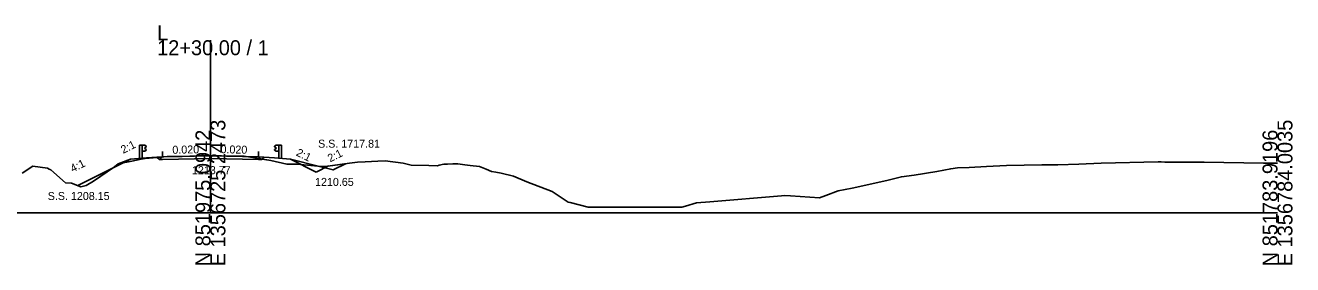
# Model space of a CAD drawing. Extents: x -26 to 4603, y -10 to 4066.
# Drawn here: x 1565.3 to 1802.8, y 490.3 to 535.2 of the extents above; entities that cross this region are included whole.
import ezdxf

# ---------------------------------------------------------------- set-up
doc = ezdxf.new("R2010")
doc.units = 0
for name, color, linetype in [('Exist Cross Section Cell', 7, 'Continuous'), ('Exist XS Center Line Elevation Label', 7, 'Continuous'), ('Exist XS Ground Line', 7, 'Continuous'), ('Prop XS Ditch Standard Text', 7, 'Continuous'), ('Prop XS Dump Level', 7, 'Continuous'), ('Prop XS Earthwork Shape', 7, 'Continuous'), ('Prop XS EOT Tick Mark', 7, 'Continuous'), ('Prop XS Finish Grade', 7, 'Continuous'), ('Prop XS Finish Grade Earthwork', 7, 'Continuous'), ('Prop XS Finish Grade Pavement', 7, 'Continuous'), ('Prop XS Guardrail', 7, 'Continuous'), ('Prop XS Pvmt Edge Slope', 7, 'Continuous'), ('Prop XS SE Text', 7, 'Continuous'), ('Prop XS Side Slope Text', 7, 'Continuous'), ('Prop XS SS Elevation Text', 7, 'Continuous'), ('Prop XS Subgrade Earthwork', 7, 'Continuous')]:
    doc.layers.add(name, color=color, linetype=linetype)

msp = doc.modelspace()

# ---------------------------------------------------------------- linework, layer by layer
at = {"layer": 'Exist Cross Section Cell'}
for p, q in [((1600, 500), (1600, 532.38)), ((1400, 500), (1600, 500)), ((1600, 500), (1800, 500))]:
    msp.add_line(p, q, dxfattribs=at)
at = {"layer": 'Exist XS Ground Line'}
msp.add_lwpolyline([(1564.7, 507.43), (1566.73, 508.78), (1569.45, 508.41), (1569.76, 508.23), (1570.09, 508.1), (1572.83, 505.68), (1573.95, 505.59), (1575.71, 504.93), (1576.74, 505.16), (1578.1, 505.99), (1582.04, 508.66), (1582.72, 509.22), (1585.3, 509.72), (1587, 510.1), (1587.78, 510.23), (1591.87, 510.58), (1594.68, 510.61), (1598.96, 510.79), (1600, 510.77), (1604.15, 510.66), (1606.35, 510.64), (1609.14, 510.2), (1611.34, 509.83), (1614.31, 509.15), (1616.19, 509.12), (1620.79, 508.72), (1621.51, 508.73), (1626.05, 509.34), (1627.58, 509.51), (1628.98, 509.6), (1631.4, 509.71), (1632.78, 509.78), (1636.14, 509.33), (1637.63, 508.98), (1640.96, 508.87), (1642.53, 508.85), (1642.9, 508.95), (1643.74, 509.13), (1644.44, 509.12), (1645.44, 509.19), (1646.38, 509.2), (1647.68, 509.01), (1648.67, 508.91), (1650.42, 508.74), (1651.71, 508.21), (1652.68, 507.8), (1653.5, 507.63), (1654.49, 507.48), (1656.8, 506.91), (1659.29, 505.81), (1664.06, 504.02), (1667.08, 502.02), (1667.13, 502.02), (1667.45, 501.94), (1670.77, 501.07), (1677.91, 501.07), (1688.37, 501.07), (1689.07, 501.27), (1691.13, 501.87), (1693.58, 502.11), (1707.06, 503.24), (1707.61, 503.26), (1708.74, 503.19), (1714.18, 502.81), (1715.36, 503.29), (1717.65, 504.15), (1720.27, 504.62), (1726.79, 506.11), (1729.51, 506.8), (1731.87, 507.08), (1736.13, 507.77), (1738.76, 508.29), (1740.03, 508.44), (1742.19, 508.5), (1745.46, 508.69), (1749.2, 508.9), (1755.86, 509.03), (1758.84, 509.04), (1762.78, 509.15), (1766.92, 509.33), (1777.64, 509.56), (1778.17, 509.56), (1778.86, 509.54), (1780.77, 509.54), (1786.27, 509.5), (1797.35, 509.34), (1798.6, 509.32), (1800, 509.31)], dxfattribs=at)
at = {"layer": 'Prop XS Dump Level'}
for p, q in [((1591, 510.55), (1600, 510.73)), ((1600, 510.73), (1609, 510.55))]:
    msp.add_line(p, q, dxfattribs=at)
at = {"layer": 'Prop XS Earthwork Shape'}
for points in [[(1590.03, 510.42), (1591.87, 510.58), (1594.68, 510.61), (1598.96, 510.79), (1600, 510.77), (1604.15, 510.66), (1606.35, 510.64), (1609.14, 510.2), (1609.67, 510.11), (1609.55, 510), (1609, 510.01), (1600, 510.19), (1591, 510.01), (1590.45, 510)], [(1590.45, 510), (1590.03, 510.42), (1591.87, 510.58), (1594.68, 510.61), (1598.96, 510.79), (1600, 510.77), (1604.15, 510.66), (1606.35, 510.64), (1609.14, 510.2), (1609.67, 510.11), (1609.55, 510), (1609, 510.01), (1600, 510.19), (1591, 510.01)], [(1575.14, 505.15), (1575.71, 504.93), (1576.74, 505.16), (1578.1, 505.99), (1581.66, 508.4)], [(1583.66, 509.4), (1581.66, 508.4), (1582.04, 508.66), (1582.72, 509.22)], [(1588, 510.31), (1585, 510.07), (1582.72, 509.22), (1585.3, 509.72), (1587, 510.1), (1587.78, 510.23), (1590.03, 510.42), (1589.98, 510.47)], [(1588, 510.31), (1585, 510.07), (1583.66, 509.4), (1585.3, 509.72), (1587, 510.1), (1587.78, 510.23), (1590.03, 510.42), (1589.98, 510.47)], [(1609.67, 510.11), (1611.34, 509.83), (1614.31, 509.15), (1616.19, 509.12), (1620.2, 508.77), (1615, 510.07), (1612, 510.31), (1610.02, 510.47)], [(1612, 510.31), (1615, 510.07), (1620.2, 508.77), (1616.19, 509.12), (1614.31, 509.15), (1611.34, 509.83), (1609.67, 510.11), (1610.02, 510.47)], [(1620.2, 508.77), (1620.79, 508.72), (1621.51, 508.73), (1625.33, 509.24), (1623, 508.07)], [(1623, 508.07), (1625.33, 509.24), (1621.51, 508.73), (1620.79, 508.72), (1620.2, 508.77)]]:
    msp.add_lwpolyline(points, close=True, dxfattribs=at)
at = {"layer": 'Prop XS EOT Tick Mark'}
for p, q in [((1591, 510.55), (1591, 511.55)), ((1609, 510.55), (1609, 511.55))]:
    msp.add_line(p, q, dxfattribs=at)
at = {"layer": 'Prop XS Finish Grade'}
for p, q in [((1591, 510.55), (1589.98, 510.47)), ((1609, 510.55), (1610.02, 510.47))]:
    msp.add_line(p, q, dxfattribs=at)
at = {"layer": 'Prop XS Finish Grade Earthwork'}
for p, q in [((1585, 510.07), (1575.14, 505.15)), ((1588, 510.31), (1585, 510.07)), ((1589.98, 510.47), (1588, 510.31)), ((1610.02, 510.47), (1612, 510.31)), ((1612, 510.31), (1615, 510.07)), ((1615, 510.07), (1619.84, 507.65)), ((1619.84, 507.65), (1622.16, 508.81))]:
    msp.add_line(p, q, dxfattribs=at)
at = {"layer": 'Prop XS Finish Grade Pavement'}
for p, q in [((1591, 510.55), (1600, 510.73)), ((1600, 510.73), (1609, 510.55))]:
    msp.add_line(p, q, dxfattribs=at)
at = {"layer": 'Prop XS Guardrail'}
for p, q in [((1586.68, 512.71), (1587.18, 512.71)), ((1586.68, 510.21), (1586.68, 512.71)), ((1587.18, 512.71), (1587.68, 512.71)), ((1587.18, 512.71), (1587.18, 510.21)), ((1587.68, 511.57), (1587.18, 511.57)), ((1587.68, 512.71), (1587.97, 512.51)), ((1587.97, 512.39), (1587.68, 512.19)), ((1587.68, 512.19), (1587.68, 512.09)), ((1587.68, 512.09), (1587.97, 511.89)), ((1587.97, 511.77), (1587.68, 511.57)), ((1587.97, 512.51), (1588, 512.45)), ((1588, 512.45), (1587.97, 512.39)), ((1587.97, 511.89), (1588, 511.83)), ((1588, 511.83), (1587.97, 511.77)), ((1612.03, 512.51), (1612, 512.45)), ((1612, 512.45), (1612.03, 512.39)), ((1612.03, 511.89), (1612, 511.83)), ((1612, 511.83), (1612.03, 511.77)), ((1612.32, 512.71), (1612.03, 512.51)), ((1612.03, 512.39), (1612.32, 512.19)), ((1612.32, 512.09), (1612.03, 511.89)), ((1612.03, 511.77), (1612.32, 511.57)), ((1612.82, 512.71), (1612.32, 512.71)), ((1612.32, 512.19), (1612.32, 512.09)), ((1612.32, 511.57), (1612.82, 511.57)), ((1613.32, 512.71), (1612.82, 512.71)), ((1612.82, 512.71), (1612.82, 510.21)), ((1613.32, 510.21), (1613.32, 512.71))]:
    msp.add_line(p, q, dxfattribs=at)
at = {"layer": 'Prop XS Pvmt Edge Slope'}
for p, q in [((1591, 510.55), (1590.45, 510)), ((1609, 510.55), (1609.55, 510))]:
    msp.add_line(p, q, dxfattribs=at)
at = {"layer": 'Prop XS Subgrade Earthwork'}
for p, q in [((1590.45, 510), (1589.98, 510.47)), ((1591, 510.01), (1590.45, 510)), ((1600, 510.19), (1591, 510.01)), ((1609, 510.01), (1600, 510.19)), ((1609, 510.01), (1609.55, 510)), ((1609.55, 510), (1610.02, 510.47))]:
    msp.add_line(p, q, dxfattribs=at)

# ---------------------------------------------------------------- texts
at = {"layer": 'Exist Cross Section Cell'}
for s, p in [('L', (1590, 532.38)), ('12+30.00 / 1', (1590, 529.58))]:
    msp.add_text(s, height=2.8, dxfattribs=at).set_placement(p)
for s, p in [('E 1356725.2473', (1602.8, 490)), ('N 851783.9196', (1800, 490)), ('E 1356784.0035', (1802.8, 490)), ('N 851975.0942', (1600, 490))]:
    msp.add_text(s, height=2.8, rotation=90, dxfattribs=at).set_placement(p)
at = {"layer": 'Exist XS Center Line Elevation Label'}
msp.add_text('1213.77', height=1.5, dxfattribs=at).set_placement((1596.54, 507.27))
at = {"layer": 'Prop XS Ditch Standard Text'}
msp.add_text('1210.65', height=1.5, dxfattribs=at).set_placement((1619.61, 505.07))
at = {"layer": 'Prop XS Dump Level'}
for s, height, p in [('Case1', 0.04, (1588, 510.27)), ('Case1', 0.04, (1612, 510.27)), ('S.S. 1208.15', 1.5, (1569.51, 502.43))]:
    msp.add_text(s, height=height, dxfattribs=at).set_placement(p)
at = {"layer": 'Prop XS SE Text'}
for rotation, p in [(1.1458, (1592.88, 511.09)), (358.8542, (1601.88, 511.2))]:
    msp.add_text('0.020', height=1.5, rotation=rotation, dxfattribs=at).set_placement(p)
at = {"layer": 'Prop XS Side Slope Text'}
for s, rotation, p in [('2:1', 26.5651, (1583.66, 511.08)), ('2:1', 333.4349, (1615.92, 510.83)), ('2:1', 26.5651, (1622.43, 509.47)), ('4:1', 26.5651, (1574.19, 507.56))]:
    msp.add_text(s, height=1.5, rotation=rotation, dxfattribs=at).set_placement(p)
at = {"layer": 'Prop XS SS Elevation Text'}
msp.add_text('S.S. 1717.81', height=1.5, dxfattribs=at).set_placement((1620.18, 512.24))

doc.saveas('drawing.dxf')
